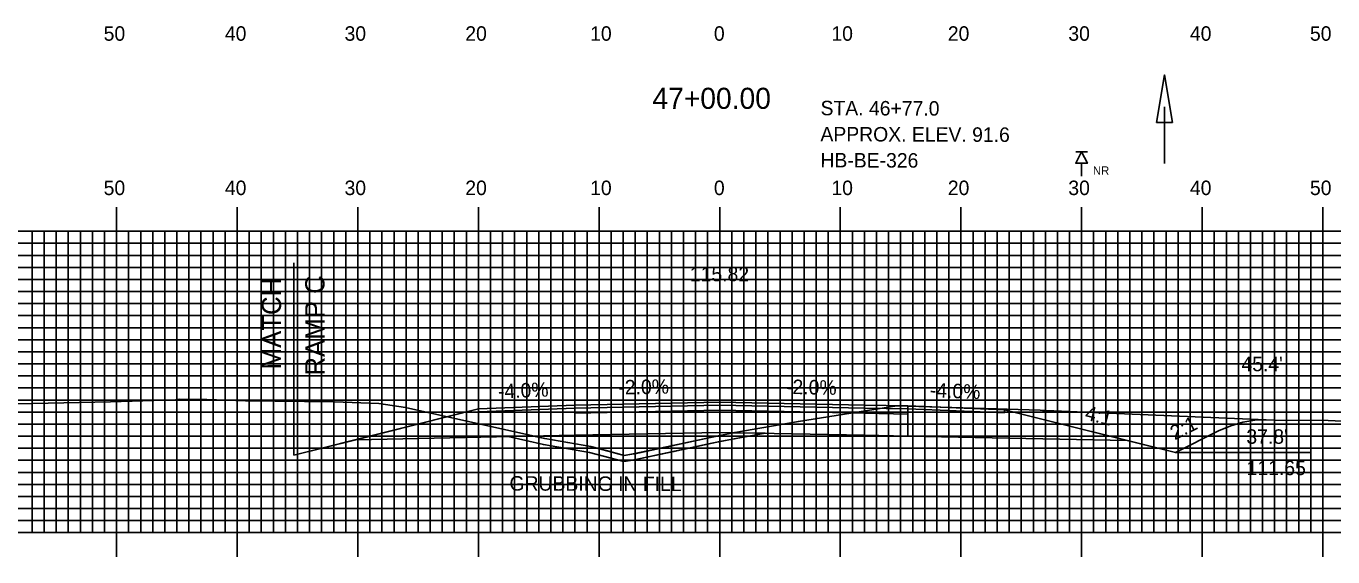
# Model space of a CAD drawing. Extents: x 1754314 to 1754654, y 442591 to 442811.
# Drawn here: x 1754422.5 to 1754530.8, y 442696.7 to 442740.7 of the extents above; entities that cross this region are included whole.
import ezdxf

# ---------------------------------------------------------------- set-up
doc = ezdxf.new("R2010")
doc.units = 0
for name, color, linetype in [('ANNOTATION', 7, 'Continuous'), ('BORING - NO REFUSAL', 7, 'Continuous'), ('D_Drainage_Ditch_Line', 7, 'Continuous'), ('D_Roadway_Centerline', 7, 'Continuous'), ('D_Roadway_Centerline_Text', 7, 'Continuous'), ('D_Roadway_Edge_Shoulder', 7, 'Continuous'), ('D_Roadway_Edge_TW', 7, 'Continuous'), ('D_Roadway_Pavement', 7, 'Continuous'), ('D_Roadway_SlopeLines', 7, 'Continuous'), ('D_Roadway_SubGrade', 7, 'Continuous'), ('D_Text_Standard', 7, 'Continuous'), ('GRUBBING IN FILL', 7, 'Continuous'), ('H_V ANNOTATION', 7, 'Continuous'), ('M_Roadway_Centerline', 7, 'Continuous'), ('MAJOR', 7, 'Continuous'), ('MINOR', 7, 'Continuous'), ('PDRAIN', 7, 'Continuous'), ('S_Roadway_Centerline', 7, 'Continuous')]:
    doc.layers.add(name, color=color, linetype=linetype)

msp = doc.modelspace()

# ---------------------------------------------------------------- linework, layer by layer
at = {"layer": 'BORING - NO REFUSAL'}
for p, q in [((1754510.48, 442730.27), (1754509.52, 442730.27)), ((1754510, 442729.31), (1754510, 442728.25))]:
    msp.add_line(p, q, dxfattribs=at)
msp.add_lwpolyline([(1754510, 442730.27), (1754510.48, 442729.31), (1754509.52, 442729.31)], close=True, dxfattribs=at)
at = {"layer": 'D_Drainage_Ditch_Line'}
msp.add_line((1754516.88, 442734), (1754516.88, 442729.3), dxfattribs=at)
msp.add_lwpolyline([(1754517.53, 442732.69), (1754516.22, 442732.69), (1754516.88, 442736.63)], close=True, dxfattribs=at)
at = {"layer": 'D_Roadway_Centerline'}
msp.add_lwpolyline([(1754444.69, 442705.1), (1754449.83, 442706.38), (1754460, 442708.93), (1754468, 442709.25), (1754480, 442709.49), (1754492, 442709.25), (1754495.6, 442709.18), (1754503.6, 442708.86), (1754513.78, 442706.31), (1754517.78, 442705.31), (1754521.36, 442707.11), (1754522.36, 442707.54), (1754523.36, 442707.83), (1754524.36, 442707.99), (1754525.36, 442708.02)], dxfattribs=at)
at = {"layer": 'D_Roadway_Edge_Shoulder'}
for points in [[(1754468, 442709.25), (1754460, 442708.93), (1754460, 442708.68), (1754468, 442709)], [(1754495.6, 442709.18), (1754503.6, 442708.86), (1754503.6, 442708.61), (1754495.6, 442708.93)]]:
    msp.add_lwpolyline(points, close=True, dxfattribs=at)
at = {"layer": 'D_Roadway_Edge_TW'}
for points in [[(1754468, 442709), (1754468, 442709.25), (1754480, 442709.49), (1754492, 442709.25), (1754492, 442709), (1754480, 442709.24)], [(1754492, 442709.25), (1754495.6, 442709.18), (1754495.6, 442708.93), (1754492, 442709)]]:
    msp.add_lwpolyline(points, close=True, dxfattribs=at)
at = {"layer": 'D_Roadway_Pavement'}
for points in [[(1754468, 442708.58), (1754468, 442709), (1754480, 442709.24), (1754492, 442709), (1754492, 442708.58), (1754480, 442708.82)], [(1754492, 442709), (1754495.6, 442708.93), (1754495.6, 442708.51), (1754492, 442708.58)]]:
    msp.add_lwpolyline(points, close=True, dxfattribs=at)
msp.add_lwpolyline([(1754495.6, 442708.93), (1754495.6, 442708.51)], dxfattribs=at)
msp.add_lwpolyline([(1754495.6, 442708.93), (1754495.6, 442708.51)], dxfattribs=at)
msp.add_lwpolyline([(1754495.6, 442708.93), (1754495.6, 442708.51)], dxfattribs=at)
at = {"layer": 'D_Roadway_SlopeLines'}
msp.add_line((1754444.69, 442705.1), (1754444.69, 442712.62), dxfattribs=at)
for points in [[(1754460, 442708.93), (1754444.69, 442705.1)], [(1754503.6, 442708.86), (1754517.78, 442705.31)], [(1754517.78, 442705.31), (1754521.36, 442707.11), (1754522.36, 442707.54), (1754523.36, 442707.83), (1754524.36, 442707.99), (1754525.36, 442708.02)]]:
    msp.add_lwpolyline(points, dxfattribs=at)
at = {"layer": 'D_Roadway_SubGrade'}
msp.add_line((1754444.69, 442721.05), (1754444.69, 442705.1), dxfattribs=at)
for points in [[(1754460, 442708.68), (1754468, 442709), (1754468, 442708.58), (1754468, 442706.75), (1754449.83, 442706.38), (1754460, 442708.93)], [(1754468, 442706.75), (1754468, 442708.58), (1754480, 442708.82), (1754492, 442708.58), (1754492, 442706.75), (1754480, 442706.99)], [(1754492, 442708.58), (1754495.6, 442708.51), (1754495.6, 442706.68), (1754492, 442706.75)], [(1754495.6, 442708.51), (1754495.6, 442708.93), (1754503.6, 442708.61), (1754503.6, 442708.86), (1754513.78, 442706.31), (1754495.6, 442706.68)]]:
    msp.add_lwpolyline(points, close=True, dxfattribs=at)
at = {"layer": 'GRUBBING IN FILL'}
msp.add_lwpolyline([(1754462.46, 442706.64), (1754465.39, 442705.98), (1754469.21, 442705.33), (1754472.06, 442704.57), (1754472.79, 442704.69), (1754473.05, 442704.73), (1754479.35, 442706.08), (1754481.34, 442706.49), (1754483.78, 442706.91)], dxfattribs=at)
msp.add_lwpolyline([(1754462.46, 442706.64), (1754465.39, 442705.98), (1754469.21, 442705.33), (1754472.06, 442704.57), (1754472.79, 442704.69), (1754473.05, 442704.73), (1754479.35, 442706.08), (1754481.34, 442706.49), (1754483.78, 442706.91)], dxfattribs=at)
for points in [[(1754483.78, 442706.91), (1754480, 442706.22), (1754480, 442706.73), (1754481.15, 442706.96)], [(1754483.78, 442706.91), (1754480, 442706.22), (1754480, 442706.73), (1754481.15, 442706.96)], [(1754480, 442706.73), (1754480, 442706.22), (1754476.2, 442705.4), (1754473.05, 442704.73), (1754472.06, 442704.57), (1754469.21, 442705.33), (1754467.3, 442705.65), (1754465.39, 442705.98), (1754463.93, 442706.31), (1754462.46, 442706.64), (1754464.57, 442706.68), (1754465.49, 442706.47), (1754467.4, 442706.14), (1754469.32, 442705.81), (1754470.7, 442705.45), (1754472.08, 442705.08), (1754472.84, 442705.2), (1754476.11, 442705.9)], [(1754480, 442706.73), (1754480, 442706.22), (1754476.2, 442705.4), (1754473.05, 442704.73), (1754472.06, 442704.57), (1754469.21, 442705.33), (1754467.3, 442705.65), (1754465.39, 442705.98), (1754463.93, 442706.31), (1754462.46, 442706.64), (1754464.57, 442706.68), (1754465.49, 442706.47), (1754467.4, 442706.14), (1754469.32, 442705.81), (1754470.7, 442705.45), (1754472.08, 442705.08), (1754472.84, 442705.2), (1754476.11, 442705.9)]]:
    msp.add_lwpolyline(points, close=True, dxfattribs=at)
at = {"layer": 'MAJOR'}
for p, q in [((1754430, 442725.67), (1754430, 442723.67)), ((1754440, 442725.67), (1754440, 442723.67)), ((1754450, 442725.67), (1754450, 442723.67)), ((1754460, 442725.67), (1754460, 442723.67)), ((1754470, 442725.67), (1754470, 442723.67)), ((1754480, 442725.67), (1754480, 442723.67)), ((1754490, 442725.67), (1754490, 442723.67)), ((1754500, 442725.67), (1754500, 442723.67)), ((1754510, 442725.67), (1754510, 442723.67)), ((1754520, 442725.67), (1754520, 442723.67)), ((1754530, 442725.67), (1754530, 442723.67)), ((1754340, 442723.67), (1754620, 442723.67)), ((1754340, 442723.67), (1754620, 442723.67)), ((1754430, 442698.67), (1754430, 442723.67)), ((1754440, 442698.67), (1754440, 442723.67)), ((1754450, 442698.67), (1754450, 442723.67)), ((1754460, 442698.67), (1754460, 442723.67)), ((1754470, 442698.67), (1754470, 442723.67)), ((1754480, 442698.67), (1754480, 442723.67)), ((1754490, 442698.67), (1754490, 442723.67)), ((1754500, 442698.67), (1754500, 442723.67)), ((1754510, 442698.67), (1754510, 442723.67)), ((1754520, 442698.67), (1754520, 442723.67)), ((1754530, 442698.67), (1754530, 442723.67)), ((1754340, 442718.67), (1754620, 442718.67)), ((1754340, 442713.67), (1754620, 442713.67)), ((1754340, 442708.67), (1754620, 442708.67)), ((1754340, 442703.67), (1754620, 442703.67)), ((1754340, 442698.67), (1754620, 442698.67)), ((1754340, 442698.67), (1754620, 442698.67)), ((1754430, 442696.66), (1754430, 442698.67)), ((1754440, 442696.66), (1754440, 442698.67)), ((1754450, 442696.66), (1754450, 442698.67)), ((1754460, 442696.66), (1754460, 442698.67)), ((1754470, 442696.66), (1754470, 442698.67)), ((1754480, 442696.66), (1754480, 442698.67)), ((1754490, 442696.66), (1754490, 442698.67)), ((1754500, 442696.66), (1754500, 442698.67)), ((1754510, 442696.66), (1754510, 442698.67)), ((1754520, 442696.66), (1754520, 442698.67)), ((1754530, 442696.66), (1754530, 442698.67))]:
    msp.add_line(p, q, dxfattribs=at)
at = {"layer": 'MINOR'}
for p, q in [((1754423, 442698.67), (1754423, 442723.67)), ((1754424, 442698.67), (1754424, 442723.67)), ((1754425, 442698.67), (1754425, 442723.67)), ((1754426, 442698.67), (1754426, 442723.67)), ((1754427, 442698.67), (1754427, 442723.67)), ((1754428, 442698.67), (1754428, 442723.67)), ((1754429, 442698.67), (1754429, 442723.67)), ((1754431, 442698.67), (1754431, 442723.67)), ((1754432, 442698.67), (1754432, 442723.67)), ((1754433, 442698.67), (1754433, 442723.67)), ((1754434, 442698.67), (1754434, 442723.67)), ((1754435, 442698.67), (1754435, 442723.67)), ((1754436, 442698.67), (1754436, 442723.67)), ((1754437, 442698.67), (1754437, 442723.67)), ((1754438, 442698.67), (1754438, 442723.67)), ((1754439, 442698.67), (1754439, 442723.67)), ((1754441, 442698.67), (1754441, 442723.67)), ((1754442, 442698.67), (1754442, 442723.67)), ((1754443, 442698.67), (1754443, 442723.67)), ((1754444, 442698.67), (1754444, 442723.67)), ((1754445, 442698.67), (1754445, 442723.67)), ((1754446, 442698.67), (1754446, 442723.67)), ((1754447, 442698.67), (1754447, 442723.67)), ((1754448, 442698.67), (1754448, 442723.67)), ((1754449, 442698.67), (1754449, 442723.67)), ((1754451, 442698.67), (1754451, 442723.67)), ((1754452, 442698.67), (1754452, 442723.67)), ((1754453, 442698.67), (1754453, 442723.67)), ((1754454, 442698.67), (1754454, 442723.67)), ((1754455, 442698.67), (1754455, 442723.67)), ((1754456, 442698.67), (1754456, 442723.67)), ((1754457, 442698.67), (1754457, 442723.67)), ((1754458, 442698.67), (1754458, 442723.67)), ((1754459, 442698.67), (1754459, 442723.67)), ((1754461, 442698.67), (1754461, 442723.67)), ((1754462, 442698.67), (1754462, 442723.67)), ((1754463, 442698.67), (1754463, 442723.67)), ((1754464, 442698.67), (1754464, 442723.67)), ((1754465, 442698.67), (1754465, 442723.67)), ((1754466, 442698.67), (1754466, 442723.67)), ((1754467, 442698.67), (1754467, 442723.67)), ((1754468, 442698.67), (1754468, 442723.67)), ((1754469, 442698.67), (1754469, 442723.67)), ((1754471, 442698.67), (1754471, 442723.67)), ((1754472, 442698.67), (1754472, 442723.67)), ((1754473, 442698.67), (1754473, 442723.67)), ((1754474, 442698.67), (1754474, 442723.67)), ((1754475, 442698.67), (1754475, 442723.67)), ((1754476, 442698.67), (1754476, 442723.67)), ((1754477, 442698.67), (1754477, 442723.67)), ((1754478, 442698.67), (1754478, 442723.67)), ((1754479, 442698.67), (1754479, 442723.67)), ((1754481, 442698.67), (1754481, 442723.67)), ((1754482, 442698.67), (1754482, 442723.67)), ((1754483, 442698.67), (1754483, 442723.67)), ((1754484, 442698.67), (1754484, 442723.67)), ((1754485, 442698.67), (1754485, 442723.67)), ((1754486, 442698.67), (1754486, 442723.67)), ((1754487, 442698.67), (1754487, 442723.67)), ((1754488, 442698.67), (1754488, 442723.67)), ((1754489, 442698.67), (1754489, 442723.67)), ((1754491, 442698.67), (1754491, 442723.67)), ((1754492, 442698.67), (1754492, 442723.67)), ((1754493, 442698.67), (1754493, 442723.67)), ((1754494, 442698.67), (1754494, 442723.67)), ((1754495, 442698.67), (1754495, 442723.67)), ((1754496, 442698.67), (1754496, 442723.67)), ((1754497, 442698.67), (1754497, 442723.67)), ((1754498, 442698.67), (1754498, 442723.67)), ((1754499, 442698.67), (1754499, 442723.67)), ((1754501, 442698.67), (1754501, 442723.67)), ((1754502, 442698.67), (1754502, 442723.67)), ((1754503, 442698.67), (1754503, 442723.67)), ((1754504, 442698.67), (1754504, 442723.67)), ((1754505, 442698.67), (1754505, 442723.67)), ((1754506, 442698.67), (1754506, 442723.67)), ((1754507, 442698.67), (1754507, 442723.67)), ((1754508, 442698.67), (1754508, 442723.67)), ((1754509, 442698.67), (1754509, 442723.67)), ((1754511, 442698.67), (1754511, 442723.67)), ((1754512, 442698.67), (1754512, 442723.67)), ((1754513, 442698.67), (1754513, 442723.67)), ((1754514, 442698.67), (1754514, 442723.67)), ((1754515, 442698.67), (1754515, 442723.67)), ((1754516, 442698.67), (1754516, 442723.67)), ((1754517, 442698.67), (1754517, 442723.67)), ((1754518, 442698.67), (1754518, 442723.67)), ((1754519, 442698.67), (1754519, 442723.67)), ((1754521, 442698.67), (1754521, 442723.67)), ((1754522, 442698.67), (1754522, 442723.67)), ((1754523, 442698.67), (1754523, 442723.67)), ((1754524, 442698.67), (1754524, 442723.67)), ((1754525, 442698.67), (1754525, 442723.67)), ((1754526, 442698.67), (1754526, 442723.67)), ((1754527, 442698.67), (1754527, 442723.67)), ((1754528, 442698.67), (1754528, 442723.67)), ((1754529, 442698.67), (1754529, 442723.67)), ((1754340, 442722.67), (1754620, 442722.67)), ((1754340, 442721.67), (1754620, 442721.67)), ((1754340, 442720.67), (1754620, 442720.67)), ((1754340, 442719.67), (1754620, 442719.67)), ((1754340, 442717.67), (1754620, 442717.67)), ((1754340, 442716.67), (1754620, 442716.67)), ((1754340, 442715.67), (1754620, 442715.67)), ((1754340, 442714.67), (1754620, 442714.67)), ((1754340, 442712.67), (1754620, 442712.67)), ((1754340, 442711.67), (1754620, 442711.67)), ((1754340, 442710.67), (1754620, 442710.67)), ((1754340, 442709.67), (1754620, 442709.67)), ((1754340, 442707.67), (1754620, 442707.67)), ((1754340, 442706.67), (1754620, 442706.67)), ((1754340, 442705.67), (1754620, 442705.67)), ((1754340, 442704.67), (1754620, 442704.67)), ((1754340, 442702.67), (1754620, 442702.67)), ((1754340, 442701.67), (1754620, 442701.67)), ((1754340, 442700.67), (1754620, 442700.67)), ((1754340, 442699.67), (1754620, 442699.67))]:
    msp.add_line(p, q, dxfattribs=at)
at = {"layer": 'PDRAIN'}
msp.add_line((1754517.78, 442705.31), (1754529.05, 442705.31), dxfattribs=at)
at = {"layer": 'S_Roadway_Centerline'}
msp.add_lwpolyline([(1754412.07, 442709.27), (1754423.02, 442709.39), (1754429.5, 442709.52), (1754434.88, 442709.69), (1754435.2, 442709.73), (1754437.49, 442709.72), (1754440.68, 442709.6), (1754448.03, 442709.52), (1754451.75, 442709.38), (1754453.94, 442709.05), (1754465.49, 442706.47), (1754469.32, 442705.81), (1754472.08, 442705.08), (1754472.72, 442705.19), (1754472.97, 442705.22), (1754479.24, 442706.57), (1754481.25, 442706.99), (1754486.53, 442707.89), (1754494.68, 442709.2), (1754506.57, 442708.82), (1754506.75, 442708.81), (1754507.04, 442708.8), (1754525.94, 442707.99), (1754530.43, 442707.96), (1754538.14, 442707.62)], dxfattribs=at)

# ---------------------------------------------------------------- texts
at = {"layer": 'ANNOTATION'}
for s, height, rotation, p in [('RAMP C', 1.6, 90, (1754447.24, 442711.7)), ('MATCH', 1.6, 90, (1754443.64, 442712.21)), ('-4.0%', 1.2, 2.2906, (1754461.64, 442709.79)), ('-2.0%', 1.2, 1.1458, (1754471.61, 442710.12)), ('-2.0%', 1.2, 358.8542, (1754485.49, 442710.18)), ('-4.0%', 1.2, 357.7094, (1754497.4, 442709.91)), ('4:1', 1.2, 345.9638, (1754510.2, 442708.07)), ('2:1', 1.2, 26.5651, (1754517.72, 442706.32))]:
    msp.add_text(s, height=height, rotation=rotation, dxfattribs=at).set_placement(p)
for s, p in [("37.8'", (1754523.66, 442706.04)), ('111.65', (1754523.68, 442703.44))]:
    msp.add_text(s, height=1.2, dxfattribs=at).set_placement(p)
at = {"layer": 'BORING - NO REFUSAL'}
for s, p in [('STA. 46+77.0', (1754488.36, 442733.29)), ('APPROX. ELEV. 91.6', (1754488.35, 442731.13)), ('HB-BE-326', (1754488.35, 442728.97))]:
    msp.add_text(s, height=1.2, rotation=359.8142, dxfattribs=at).set_placement(p)
msp.add_text('NR', height=0.7, dxfattribs=at).set_placement((1754510.94, 442728.35))
at = {"layer": 'D_Roadway_Centerline'}
for s, p in [('C', (1754480, 442709.49)), ('L', (1754480, 442709.48))]:
    msp.add_text(s, height=0.0146, dxfattribs=at).set_placement(p)
at = {"layer": 'D_Roadway_Centerline_Text'}
msp.add_text('115.82', height=1.2, dxfattribs=at).set_placement((1754477.53, 442719.52))
at = {"layer": 'D_Text_Standard'}
msp.add_text("45.4'", height=1.2, dxfattribs=at).set_placement((1754523.25, 442712.06))
at = {"layer": 'GRUBBING IN FILL'}
msp.add_text('GRUBBING IN FILL', height=1.2, rotation=359.8142, dxfattribs=at).set_placement((1754462.57, 442702.16))
at = {"layer": 'H_V ANNOTATION'}
for s, height, p in [('50', 1.2, (1754428.93, 442739.47)), ('40', 1.2, (1754438.98, 442739.47)), ('30', 1.2, (1754448.9, 442739.47)), ('20', 1.2, (1754458.91, 442739.47)), ('10', 1.2, (1754469.26, 442739.47)), ('0', 1.2, (1754479.52, 442739.47)), ('10', 1.2, (1754489.26, 442739.47)), ('20', 1.2, (1754498.91, 442739.47)), ('30', 1.2, (1754508.9, 442739.47)), ('40', 1.2, (1754518.98, 442739.47)), ('50', 1.2, (1754528.93, 442739.47)), ('47+00.00', 1.75, (1754474.42, 442733.82)), ('50', 1.2, (1754428.93, 442726.67)), ('40', 1.2, (1754438.98, 442726.67)), ('30', 1.2, (1754448.9, 442726.67)), ('20', 1.2, (1754458.91, 442726.67)), ('10', 1.2, (1754469.26, 442726.67)), ('0', 1.2, (1754479.52, 442726.67)), ('10', 1.2, (1754489.26, 442726.67)), ('20', 1.2, (1754498.91, 442726.67)), ('30', 1.2, (1754508.9, 442726.67)), ('40', 1.2, (1754518.98, 442726.67)), ('50', 1.2, (1754528.93, 442726.67))]:
    msp.add_text(s, height=height, dxfattribs=at).set_placement(p)
at = {"layer": 'M_Roadway_Centerline'}
for s, p in [('C', (1754435.2, 442709.73)), ('L', (1754435.19, 442709.73))]:
    msp.add_text(s, height=0.0146, dxfattribs=at).set_placement(p)

doc.saveas('drawing.dxf')
